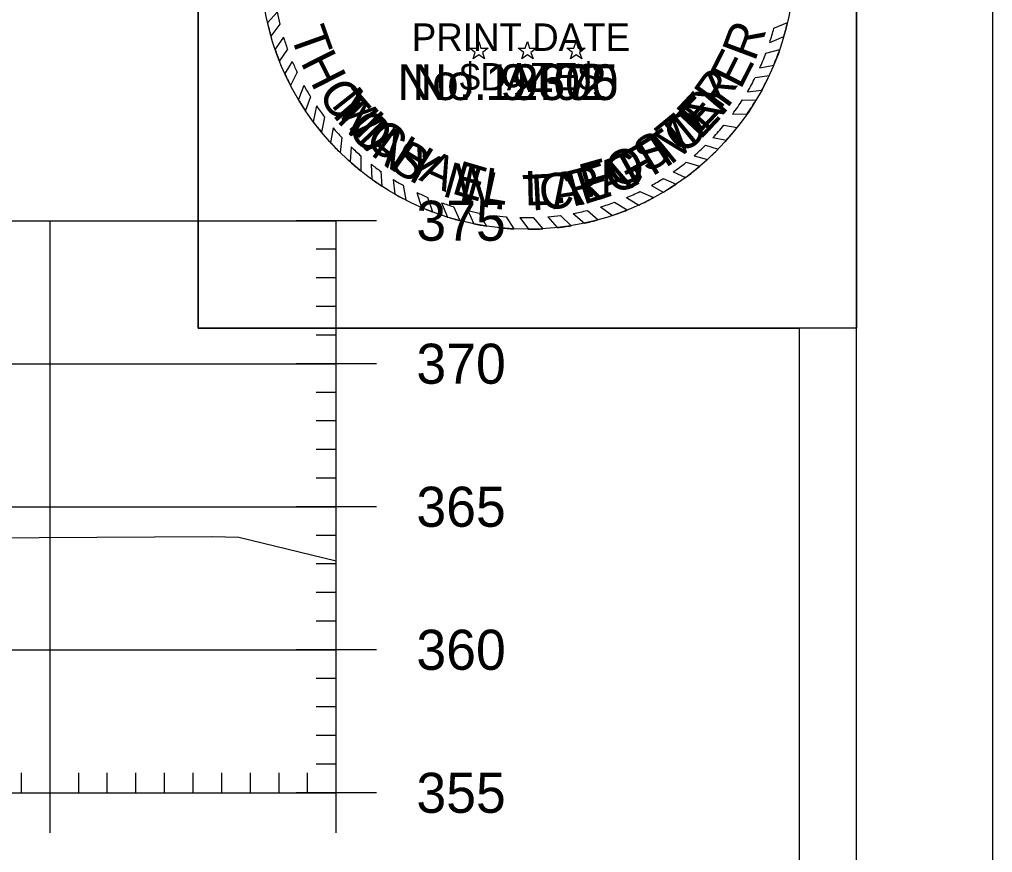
# Model space of a CAD drawing. Extents: x 1368910 to 1369601, y 380116 to 380950.
# Drawn here: x 1369209.17 to 1369243.18, y 380680.67 to 380709.8 of the extents above; entities that cross this region are included whole.
import ezdxf

# ---------------------------------------------------------------- set-up
doc = ezdxf.new("R2010")
doc.units = 0
for name, color, linetype in [('R_Axis', 7, 'Continuous'), ('R_Axis Annot', 7, 'Continuous'), ('R_Border', 7, 'Continuous'), ('R_Exist Surface', 7, 'Continuous'), ('R_Grid', 7, 'Continuous'), ('R_No Plot', 7, 'Continuous'), ('STAMP_PE_CRAFTON', 7, 'Continuous'), ('STAMP_PE_FOSTER', 7, 'Continuous'), ('STAMP_PE_SEAL-INFO', 7, 'Continuous'), ('STAMP_PE_TAEGTMEYER', 7, 'Continuous'), ('STAMP_PE_TXT', 7, 'Continuous'), ('STAMP_PRELIMINARY', 7, 'Continuous')]:
    doc.layers.add(name, color=color, linetype=linetype)

msp = doc.modelspace()

# ---------------------------------------------------------------- linework, layer by layer
at = {"layer": 'R_Axis'}
for p, q in [((1369221.644, 380702.759), (1369218.844, 380702.759)), ((1369220.244, 380682.759), (1369220.244, 380702.759)), ((1369220.244, 380701.759), (1369219.544, 380701.759)), ((1369220.244, 380700.759), (1369219.544, 380700.759)), ((1369220.244, 380699.759), (1369219.544, 380699.759)), ((1369220.244, 380698.759), (1369219.544, 380698.759)), ((1369221.644, 380697.759), (1369218.844, 380697.759)), ((1369220.244, 380696.759), (1369219.544, 380696.759)), ((1369220.244, 380695.759), (1369219.544, 380695.759)), ((1369220.244, 380694.759), (1369219.544, 380694.759)), ((1369220.244, 380693.759), (1369219.544, 380693.759)), ((1369221.644, 380692.759), (1369218.844, 380692.759)), ((1369220.244, 380691.759), (1369219.544, 380691.759)), ((1369220.244, 380690.759), (1369219.544, 380690.759)), ((1369220.244, 380689.759), (1369219.544, 380689.759)), ((1369220.244, 380688.759), (1369219.544, 380688.759)), ((1369221.644, 380687.759), (1369218.844, 380687.759)), ((1369220.244, 380686.759), (1369219.544, 380686.759)), ((1369220.244, 380685.759), (1369219.544, 380685.759)), ((1369220.244, 380684.759), (1369219.544, 380684.759)), ((1369210.244, 380681.359), (1369210.244, 380684.159)), ((1369220.244, 380681.359), (1369220.244, 380684.159)), ((1369220.244, 380683.759), (1369219.544, 380683.759)), ((1369209.244, 380682.759), (1369209.244, 380683.459)), ((1369211.244, 380682.759), (1369211.244, 380683.459)), ((1369212.244, 380682.759), (1369212.244, 380683.459)), ((1369213.244, 380682.759), (1369213.244, 380683.459)), ((1369214.244, 380682.759), (1369214.244, 380683.459)), ((1369215.244, 380682.759), (1369215.244, 380683.459)), ((1369216.244, 380682.759), (1369216.244, 380683.459)), ((1369217.244, 380682.759), (1369217.244, 380683.459)), ((1369218.244, 380682.759), (1369218.244, 380683.459)), ((1369219.244, 380682.759), (1369219.244, 380683.459)), ((1368940.244, 380682.759), (1369220.244, 380682.759)), ((1369221.644, 380682.759), (1369218.844, 380682.759))]:
    msp.add_line(p, q, dxfattribs=at)
at = {"layer": 'R_Border'}
msp.add_line((1369238.424, 380527.759), (1369238.424, 380733.219), dxfattribs=at)
at = {"layer": 'R_Exist Surface'}
msp.add_lwpolyline([(1369138.01, 380691.506), (1369148.634, 380691.718), (1369160.914, 380692.36), (1369166.365, 380692.219), (1369166.769, 380692.195), (1369176.35, 380691.942), (1369196.483, 380691.461), (1369202.629, 380691.551), (1369205.82, 380691.659), (1369215.91, 380691.722), (1369216.843, 380691.701), (1369220.244, 380690.869)], dxfattribs=at)
at = {"layer": 'R_Grid'}
for p, q in [((1368940.244, 380702.759), (1369220.244, 380702.759)), ((1369210.244, 380682.759), (1369210.244, 380702.759)), ((1369220.244, 380682.759), (1369220.244, 380702.759)), ((1368940.244, 380697.759), (1369220.244, 380697.759)), ((1368940.244, 380692.759), (1369220.244, 380692.759)), ((1368940.244, 380687.759), (1369220.244, 380687.759)), ((1368940.244, 380682.759), (1369220.244, 380682.759))]:
    msp.add_line(p, q, dxfattribs=at)
at = {"layer": 'R_No Plot'}
for points in [[(1368909.836, 380737.113), (1369243.176, 380737.113), (1369243.176, 380523.776), (1368909.836, 380523.776)], [(1369236.424, 380632.489), (1368924.244, 380632.489), (1368924.244, 380731.219), (1369173.784, 380731.219), (1369173.784, 380721.339), (1369191.324, 380721.339), (1369215.424, 380721.339), (1369215.424, 380699.006), (1369236.424, 380699.006)], [(1368924.244, 380731.219), (1369173.784, 380731.219), (1369173.784, 380721.339), (1369191.324, 380721.339), (1369215.424, 380721.339), (1369215.424, 380699.006), (1369236.424, 380699.006), (1369236.424, 380529.759), (1368924.244, 380529.759)], [(1369215.424, 380723.339), (1369238.424, 380723.339), (1369238.424, 380699.006), (1369215.424, 380699.006)]]:
    msp.add_lwpolyline(points, close=True, dxfattribs=at)
at = {"layer": 'STAMP_PE_SEAL-INFO'}
for p, q in [((1369218.181, 380710.046), (1369217.841, 380709.678)), ((1369218.274, 380709.627), (1369217.962, 380709.212)), ((1369235.537, 380709.488), (1369236.009, 380709.69)), ((1369218.398, 380709.18), (1369218.103, 380708.762)), ((1369235.39, 380708.994), (1369235.88, 380709.195)), ((1369218.539, 380708.757), (1369218.257, 380708.345)), ((1369235.255, 380708.614), (1369235.738, 380708.745)), ((1369218.705, 380708.331), (1369218.444, 380707.908)), ((1369235.041, 380708.1), (1369235.529, 380708.196)), ((1369218.877, 380707.947), (1369218.649, 380707.486)), ((1369234.88, 380707.763), (1369235.368, 380707.832)), ((1369219.112, 380707.489), (1369218.921, 380706.999)), ((1369234.608, 380707.265), (1369235.109, 380707.319)), ((1369219.348, 380707.085), (1369219.164, 380706.614)), ((1369219.55, 380706.773), (1369219.44, 380706.221)), ((1369234.436, 380706.984), (1369234.914, 380706.978)), ((1369234.097, 380706.49), (1369234.601, 380706.493)), ((1369219.831, 380706.383), (1369219.729, 380705.852)), ((1369233.789, 380706.096), (1369234.25, 380706.017)), ((1369220.135, 380706.005), (1369220.048, 380705.485)), ((1369220.437, 380705.668), (1369220.375, 380705.146)), ((1369233.151, 380705.404), (1369233.592, 380705.266)), ((1369233.406, 380705.663), (1369233.883, 380705.578)), ((1369220.76, 380705.343), (1369220.73, 380704.813)), ((1369221.104, 380705.03), (1369221.101, 380704.501)), ((1369221.464, 380704.735), (1369221.483, 380704.211)), ((1369232.474, 380704.807), (1369232.942, 380704.662)), ((1369232.745, 380705.031), (1369233.216, 380704.903)), ((1369221.803, 380704.486), (1369221.839, 380703.968)), ((1369232.014, 380704.464), (1369232.452, 380704.275)), ((1369222.23, 380704.204), (1369222.29, 380703.692)), ((1369231.67, 380704.236), (1369232.119, 380704.041)), ((1369222.58, 380703.998), (1369222.671, 380703.485)), ((1369223.061, 380703.748), (1369223.218, 380703.227)), ((1369230.848, 380703.778), (1369231.331, 380703.566)), ((1369231.255, 380703.991), (1369231.672, 380703.759)), ((1369223.433, 380703.58), (1369223.606, 380703.069)), ((1369223.926, 380703.387), (1369224.135, 380702.885)), ((1369229.969, 380703.404), (1369230.412, 380703.136)), ((1369230.388, 380703.569), (1369230.812, 380703.308)), ((1369224.336, 380703.252), (1369224.562, 380702.763)), ((1369224.844, 380703.114), (1369225.056, 380702.648)), ((1369225.241, 380703.028), (1369225.488, 380702.57)), ((1369229.017, 380703.117), (1369229.395, 380702.792)), ((1369229.476, 380703.241), (1369229.893, 380702.944)), ((1369225.741, 380702.947), (1369225.981, 380702.506)), ((1369226.178, 380702.899), (1369226.452, 380702.471)), ((1369226.663, 380702.872), (1369226.965, 380702.459)), ((1369227.122, 380702.87), (1369227.466, 380702.474)), ((1369227.641, 380702.897), (1369227.967, 380702.517)), ((1369228.079, 380702.943), (1369228.452, 380702.585)), ((1369228.524, 380703.013), (1369228.913, 380702.673))]:
    msp.add_line(p, q, dxfattribs=at)
for radius, start, end in [(8.914, 191.2274, 193.9858), (9.323, 193.0369, 195.9973), (8.914, 341.777, 345.0925), (9.323, 343.8925, 347.035), (8.914, 196.9675, 199.8353), (9.323, 198.8967, 201.6281), (8.914, 335.6038, 339.1858), (9.323, 337.3837, 340.9933), (8.914, 202.7761, 205.4791), (9.323, 204.5479, 207.4328), (9.323, 331.4037, 334.9332), (8.914, 208.7883, 211.7934), (8.914, 329.5549, 333.2076), (9.323, 210.8636, 213.6571), (8.914, 214.1838, 217.2747), (8.914, 323.5851, 327.4407), (9.323, 325.4405, 328.9872), (9.323, 216.6115, 219.491), (8.914, 316.6531, 320.3711), (8.914, 220.3909, 223.3056), (9.323, 318.2846, 321.8043), (9.323, 222.48, 225.3801), (8.914, 310.7744, 314.3161), (8.914, 226.2494, 229.2407), (9.323, 312.4518, 315.6633), (9.323, 228.3665, 231.348), (8.914, 232.229, 234.9336), (8.914, 304.823, 308.5143), (9.323, 306.3721, 310.208), (9.323, 234.295, 236.9452), (8.914, 238.2223, 240.8353), (8.914, 299.0768, 302.1724), (8.914, 244.3204, 246.9486), (8.914, 292.8745, 296.1185), (9.323, 300.621, 303.8703), (9.323, 240.1977, 242.8613), (8.914, 250.3491, 253.1216), (8.914, 286.6423, 289.9783), (9.323, 294.6481, 298.2166), (9.323, 246.576, 249.1558), (8.914, 256.505, 259.1192), (8.914, 280.3459, 283.5814), (9.323, 288.5709, 291.9733), (9.323, 252.5967, 255.3252), (8.914, 262.3783, 265.2012), (8.914, 268.3215, 271.277), (8.914, 274.6157, 277.4486), (9.323, 282.3199, 285.3702), (9.323, 258.4433, 261.1398), (9.323, 264.1978, 267.1009), (9.323, 270.2548, 273.3361), (9.323, 276.4239, 279.4357)]:
    msp.add_arc((1369226.924, 380711.781), radius, start, end, dxfattribs=at)
at = {"layer": 'STAMP_PE_TXT'}
for p, q in [((1369225.15, 380708.79), (1369225.226, 380709.023)), ((1369225.226, 380709.023), (1369225.301, 380708.79)), ((1369226.848, 380708.79), (1369226.924, 380709.023)), ((1369226.924, 380709.023), (1369226.999, 380708.79)), ((1369228.546, 380708.79), (1369228.622, 380709.023)), ((1369228.622, 380709.023), (1369228.697, 380708.79)), ((1369225.103, 380708.646), (1369224.905, 380708.79)), ((1369224.905, 380708.79), (1369225.15, 380708.79)), ((1369225.027, 380708.413), (1369225.103, 380708.646)), ((1369225.226, 380708.557), (1369225.027, 380708.413)), ((1369225.424, 380708.413), (1369225.226, 380708.557)), ((1369225.301, 380708.79), (1369225.547, 380708.79)), ((1369225.547, 380708.79), (1369225.348, 380708.646)), ((1369225.348, 380708.646), (1369225.424, 380708.413)), ((1369226.801, 380708.646), (1369226.603, 380708.79)), ((1369226.603, 380708.79), (1369226.848, 380708.79)), ((1369226.725, 380708.413), (1369226.801, 380708.646)), ((1369226.924, 380708.557), (1369226.725, 380708.413)), ((1369227.122, 380708.413), (1369226.924, 380708.557)), ((1369226.999, 380708.79), (1369227.245, 380708.79)), ((1369227.245, 380708.79), (1369227.046, 380708.646)), ((1369227.046, 380708.646), (1369227.122, 380708.413)), ((1369228.499, 380708.646), (1369228.301, 380708.79)), ((1369228.301, 380708.79), (1369228.546, 380708.79)), ((1369228.423, 380708.413), (1369228.499, 380708.646)), ((1369228.622, 380708.557), (1369228.423, 380708.413)), ((1369228.82, 380708.413), (1369228.622, 380708.557)), ((1369228.697, 380708.79), (1369228.943, 380708.79)), ((1369228.943, 380708.79), (1369228.744, 380708.646)), ((1369228.744, 380708.646), (1369228.82, 380708.413))]:
    msp.add_line(p, q, dxfattribs=at)
at = {"layer": 'STAMP_PRELIMINARY'}
msp.add_circle((1369226.924, 380711.781), 9.323, dxfattribs=at)

# ---------------------------------------------------------------- texts
at = {"layer": 'R_Axis Annot'}
for s, p in [('375', (1369223.044, 380702.059)), ('370', (1369223.044, 380697.059)), ('365', (1369223.044, 380692.059)), ('360', (1369223.044, 380687.059)), ('355', (1369223.044, 380682.059))]:
    msp.add_text(s, height=1.4, dxfattribs=at).set_placement(p)
at = {"layer": 'STAMP_PE_CRAFTON'}
msp.add_text('No. 12370', height=1.25, dxfattribs=at).set_placement((1369222.386, 380706.978))
for s, rotation, p in [('T', 310.7442, (1369219.89, 380706.679)), ('N', 49.2411, (1369233.206, 380705.803)), ('O', 317.6422, (1369220.557, 380705.868)), ('O', 41.8391, (1369232.359, 380705.022)), ('N', 324.4537, (1369221.403, 380705.083)), ('T', 34.1136, (1369231.5, 380704.42)), ('Y', 331.1686, (1369222.436, 380704.367)), ('F', 28.7821, (1369230.585, 380703.911)), ('A', 20.5125, (1369229.604, 380703.537)), ('N', 347.4752, (1369224.49, 380703.451)), ('C', 6.0117, (1369227.395, 380703.123)), ('R', 14.8189, (1369228.491, 380703.237)), ('.', 356.8926, (1369225.72, 380703.174))]:
    msp.add_text(s, height=1.25, rotation=rotation, dxfattribs=at).set_placement(p)
at = {"layer": 'STAMP_PE_FOSTER'}
msp.add_text('No. 9402', height=1.25, dxfattribs=at).set_placement((1369222.909, 380706.978))
for s, rotation, p in [('R', 54.5031, (1369233.648, 380706.592)), ('M', 308.339, (1369220.04, 380706.803)), ('E', 46.9613, (1369232.924, 380705.771)), ('I', 314.1842, (1369220.837, 380705.866)), ('T', 39.4194, (1369232.066, 380705.021)), ('C', 319.8733, (1369221.191, 380705.513)), ('S', 31.7234, (1369231.114, 380704.394)), ('H', 327.7235, (1369222.121, 380704.776)), ('A', 335.7276, (1369223.101, 380704.194)), ('O', 23.719, (1369230.003, 380703.864)), ('E', 343.5779, (1369224.239, 380703.724)), ('F', 15.8691, (1369228.959, 380703.536)), ('L', 350.8115, (1369225.298, 380703.447)), ('L', 1.2666, (1369226.837, 380703.29)), ('.', 6.8035, (1369227.884, 380703.348))]:
    msp.add_text(s, height=1.2, rotation=rotation, dxfattribs=at).set_placement(p)
at = {"layer": 'STAMP_PE_TAEGTMEYER'}
for s, rotation, p in [('T', 289.646, (1369218.618, 380709.292)), ('R', 69.57, (1369234.869, 380708.296)), ('H', 296.7339, (1369218.978, 380708.307)), ('E', 63.0984, (1369234.37, 380707.314)), ('Y', 53.9986, (1369233.701, 380706.374)), ('O', 303.7708, (1369219.571, 380707.199)), ('E', 46.8094, (1369232.962, 380705.559)), ('M', 314.2033, (1369220.226, 380706.248)), ('M', 39.3, (1369231.922, 380704.68)), ('A', 321.0594, (1369221.187, 380705.283)), ('S', 327.8239, (1369222.014, 380704.639)), ('T', 31.466, (1369231.024, 380704.136)), ('G', 23.3052, (1369229.923, 380703.643)), ('N', 344.2727, (1369223.91, 380703.633)), ('E', 17.6836, (1369228.874, 380703.313)), ('T', 3.0061, (1369226.788, 380703.102)), ('A', 8.9826, (1369227.835, 380703.157)), ('.', 350.6464, (1369225.123, 380703.301))]:
    msp.add_text(s, height=1.25, rotation=rotation, dxfattribs=at).set_placement(p)
msp.add_text('No. 19605', height=1.25, dxfattribs=at).set_placement((1369222.386, 380706.978))
at = {"layer": 'STAMP_PRELIMINARY'}
for s, p in [('PRINT DATE', (1369222.881, 380708.697)), ('$DATE$', (1369224.558, 380707.312))]:
    msp.add_text(s, height=0.96, dxfattribs=at).set_placement(p)

doc.saveas('drawing.dxf')
